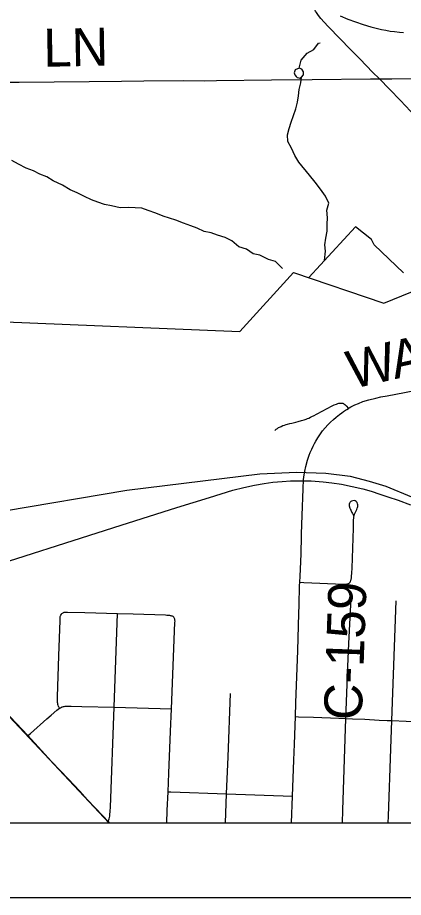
# Model space of a CAD drawing. Extents: x 0 to 34, y 0 to 22.
# Drawn here: x 14.164 to 14.741, y 9.81 to 11.126 of the extents above; entities that cross this region are included whole.
import ezdxf

# ---------------------------------------------------------------- set-up
doc = ezdxf.new("R2010")
doc.units = 0
for name, color, linetype in [('GM_X_Corporation', 7, 'Continuous'), ('GM_X_County_Road', 7, 'Continuous'), ('GM_X_County_Road_Text', 7, 'Continuous'), ('GM_X_Minor_Lake', 7, 'Continuous'), ('GM_X_Minor_River', 7, 'Continuous'), ('GM_X_Rail_Line', 7, 'Continuous'), ('GM_X_State_Route', 7, 'Continuous'), ('GM_X_Township_Road', 7, 'Continuous'), ('SH_Data', 7, 'Continuous')]:
    doc.layers.add(name, color=color, linetype=linetype)

msp = doc.modelspace()

# ---------------------------------------------------------------- linework, layer by layer
at = {"layer": 'GM_X_Corporation'}
msp.add_lwpolyline([(13.1086, 12.6609), (13.111, 11.8906), (13.114, 11.5469), (13.1204, 10.132), (13.1218, 9.9288), (13.1219, 9.9214), (18.7033, 9.9214)], dxfattribs=at)
at = {"layer": 'GM_X_County_Road'}
for p, q in [((14.5737, 9.9214), (14.5753, 9.961)), ((14.2995, 9.9234), (14.3014, 9.9214))]:
    msp.add_line(p, q, dxfattribs=at)
for points in [[(14.7052, 11.0345), (14.6952, 11.0447), (14.6764, 11.0637), (14.6612, 11.0792), (14.647, 11.0939), (14.6283, 11.1131), (14.6179, 11.1246), (14.6157, 11.1272), (14.6131, 11.1305), (14.6111, 11.1335), (14.6097, 11.1358), (14.6085, 11.1378), (14.6075, 11.1401), (14.6067, 11.1424), (14.6062, 11.1445), (14.6059, 11.1466), (14.6056, 11.1505)], [(14.127, 11.0295), (14.1666, 11.0294), (14.2711, 11.0304), (14.3194, 11.031), (14.3528, 11.0315), (14.4117, 11.0318), (14.444, 11.0317), (14.4619, 11.032), (14.5438, 11.0332), (14.6047, 11.0334), (14.692, 11.0344), (14.7052, 11.0345)], [(14.7052, 11.0345), (14.7237, 11.0347), (14.7658, 11.035), (14.8162, 11.0357), (14.8668, 11.0361), (14.9479, 11.0368), (15.0064, 11.0372), (15.0495, 11.0372)], [(14.8686, 10.8663), (14.8564, 10.879), (14.8361, 10.9), (14.8187, 10.9177), (14.8014, 10.9356), (14.7848, 10.9524), (14.7688, 10.9689), (14.7518, 10.9862), (14.7368, 11.0019), (14.7205, 11.019), (14.7052, 11.0345)], [(14.659, 10.5414), (14.66, 10.542), (14.6628, 10.5436), (14.6687, 10.5465), (14.6739, 10.5489), (14.6805, 10.5515), (14.6896, 10.5544), (14.6999, 10.5569), (14.7076, 10.5585), (14.7171, 10.5603), (14.7427, 10.5651), (14.7653, 10.5696), (14.7904, 10.5747), (14.7959, 10.5759), (14.8013, 10.5772), (14.8052, 10.5782), (14.8087, 10.5793), (14.812, 10.5805), (14.8157, 10.5819), (14.8211, 10.5842), (14.8301, 10.5886), (14.8501, 10.6)], [(14.6069, 10.5305), (14.6122, 10.5334), (14.6344, 10.545), (14.6376, 10.5465), (14.6409, 10.5479), (14.6432, 10.5487), (14.6448, 10.5491), (14.6466, 10.5493), (14.6473, 10.5494), (14.6485, 10.5494), (14.6492, 10.5494), (14.6504, 10.5491), (14.6517, 10.5486), (14.6523, 10.5483), (14.6534, 10.5473), (14.6554, 10.5453), (14.659, 10.5414)], [(14.5886, 10.3412), (14.5889, 10.3514), (14.589, 10.3538), (14.5898, 10.3811), (14.5911, 10.4209), (14.592, 10.4351), (14.5928, 10.4419), (14.5937, 10.4477), (14.5951, 10.4546), (14.5977, 10.4641), (14.6002, 10.4712), (14.6019, 10.4755), (14.6041, 10.4806), (14.6061, 10.4847), (14.6084, 10.489), (14.6104, 10.4925), (14.6134, 10.4975), (14.6162, 10.5017), (14.6204, 10.5077), (14.6242, 10.5123), (14.6281, 10.5168), (14.6322, 10.521), (14.6364, 10.5248), (14.6408, 10.5285), (14.6454, 10.5321), (14.649, 10.5348), (14.6517, 10.5367), (14.6547, 10.5387), (14.6566, 10.5399), (14.659, 10.5414)], [(14.5487, 10.5084), (14.551, 10.5101), (14.5529, 10.5115), (14.5546, 10.5126), (14.5559, 10.5133), (14.5573, 10.514), (14.5582, 10.5145), (14.5608, 10.5156), (14.5634, 10.5165), (14.5658, 10.5172), (14.5678, 10.5177), (14.5713, 10.5186), (14.5743, 10.5194), (14.5802, 10.5208), (14.584, 10.5218), (14.5889, 10.5232), (14.5926, 10.5243), (14.5956, 10.5253), (14.5979, 10.5262), (14.5999, 10.527), (14.6022, 10.5281), (14.6051, 10.5296), (14.6069, 10.5305)], [(14.5863, 10.2812), (14.5867, 10.2903), (14.5877, 10.312), (14.5881, 10.3244), (14.5885, 10.3349), (14.5886, 10.3392), (14.5886, 10.3412)], [(14.5796, 10.0803), (14.5803, 10.1011), (14.5834, 10.1794), (14.585, 10.2344), (14.5853, 10.2468), (14.586, 10.276), (14.5863, 10.2812)], [(14.1348, 10.0917), (14.1376, 10.0905), (14.1399, 10.0894), (14.1422, 10.0882), (14.1447, 10.0866), (14.1474, 10.0847), (14.1527, 10.0802), (14.1628, 10.07), (14.1796, 10.0518)], [(14.5753, 9.961), (14.5772, 10.0153), (14.5781, 10.0388), (14.5796, 10.0803)], [(14.1796, 10.0518), (14.1999, 10.0298), (14.2149, 10.0133), (14.2401, 9.9867), (14.2572, 9.9687), (14.269, 9.9559), (14.2915, 9.9319), (14.2995, 9.9234)]]:
    msp.add_lwpolyline(points, dxfattribs=at)
at = {"layer": 'GM_X_Minor_Lake'}
msp.add_line((14.5786, 11.0406), (14.5807, 11.0379), dxfattribs=at)
msp.add_lwpolyline([(14.5807, 11.0379), (14.5822, 11.0365), (14.5849, 11.0358), (14.5864, 11.0354), (14.589, 11.037), (14.5917, 11.0404), (14.5916, 11.045), (14.5893, 11.0491), (14.5851, 11.0506), (14.5791, 11.0479), (14.5776, 11.0433), (14.5786, 11.0406)], dxfattribs=at)
at = {"layer": 'GM_X_Minor_River'}
for p, q in [((14.6695, 10.8131), (14.5997, 10.737)), ((14.6935, 10.7943), (14.6695, 10.8131)), ((14.6977, 10.786), (14.6935, 10.7943)), ((14.7412, 10.7441), (14.6977, 10.786)), ((14.4966, 10.6567), (14.5766, 10.7449)), ((14.5766, 10.7449), (14.7117, 10.6989)), ((14.7117, 10.6989), (14.7655, 10.7206)), ((14.126, 10.6717), (14.4966, 10.6567))]:
    msp.add_line(p, q, dxfattribs=at)
for points in [[(14.5851, 11.0506), (14.5881, 11.0624), (14.5971, 11.0727), (14.6072, 11.0784), (14.6144, 11.088), (14.6166, 11.0884)], [(14.6231, 10.7625), (14.6248, 10.7764), (14.6236, 10.7862), (14.6254, 10.7961), (14.6272, 10.8067), (14.6271, 10.817), (14.6278, 10.8264), (14.6265, 10.8382), (14.6299, 10.8485), (14.6249, 10.8587), (14.6172, 10.8696), (14.6092, 10.8798), (14.6008, 10.8903), (14.5847, 10.9099), (14.5786, 10.9197), (14.5736, 10.9307), (14.5682, 10.9409), (14.5678, 10.9507), (14.5703, 10.9602), (14.5733, 10.9697), (14.577, 10.9796), (14.5803, 10.9895), (14.5829, 10.9998), (14.5843, 11.0093), (14.5854, 11.0187), (14.588, 11.0286), (14.5889, 11.0369)], [(14.5602, 10.7505), (14.5499, 10.761), (14.5393, 10.7643), (14.5264, 10.7707), (14.5165, 10.7725), (14.5063, 10.7796), (14.4953, 10.783), (14.4846, 10.792), (14.4747, 10.7972), (14.4633, 10.8005), (14.4535, 10.8042), (14.4432, 10.8061), (14.433, 10.8109), (14.4231, 10.8146), (14.4121, 10.8183), (14.4011, 10.8228), (14.3912, 10.8258), (14.3817, 10.8291), (14.3711, 10.8336), (14.3597, 10.8373), (14.3499, 10.841), (14.34, 10.8413), (14.3302, 10.842), (14.3177, 10.8415), (14.3048, 10.8444), (14.2942, 10.8463), (14.2843, 10.85), (14.2748, 10.8537), (14.2642, 10.8582), (14.2535, 10.8638), (14.2429, 10.8686), (14.2315, 10.8753), (14.2174, 10.8817), (14.2079, 10.8877), (14.1977, 10.8918), (14.1878, 10.897), (14.1768, 10.9007), (14.1658, 10.9067), (14.1555, 10.9123)]]:
    msp.add_lwpolyline(points, dxfattribs=at)
at = {"layer": 'GM_X_Rail_Line'}
for points in [[(14.1444, 10.3883), (14.3278, 10.419), (14.5263, 10.4433), (14.5815, 10.446), (14.6252, 10.4446), (14.6618, 10.4398), (14.6899, 10.4325), (14.7147, 10.4251), (14.7535, 10.4092), (15.1648, 10.2215), (15.268, 10.1707), (15.3613, 10.1307), (15.4037, 10.1062)], [(14.0907, 10.294), (14.3192, 10.3667), (14.4022, 10.3931), (14.451, 10.4082), (14.4862, 10.419), (14.5025, 10.4232), (14.5187, 10.4264), (14.5331, 10.429), (14.546, 10.4309), (14.56, 10.4322), (14.5724, 10.4328), (14.5852, 10.4332), (14.6034, 10.4328), (14.6211, 10.4316), (14.634, 10.4301), (14.6488, 10.4279), (14.6646, 10.4246), (14.6806, 10.4209), (14.693, 10.4176), (14.706, 10.4132), (14.7178, 10.4093), (14.7332, 10.404), (14.7516, 10.3973)], [(14.3009, 9.9214), (14.1369, 10.0957), (13.4469, 10.121), (13.3674, 10.1227)]]:
    msp.add_lwpolyline(points, dxfattribs=at)
at = {"layer": 'GM_X_State_Route'}
msp.add_lwpolyline([(14.6466, 11.1286), (14.6581, 11.1238), (14.6697, 11.1196), (14.6811, 11.1158), (14.6925, 11.1124), (14.7025, 11.1098), (14.7083, 11.1085), (14.7151, 11.1071), (14.7216, 11.106), (14.7278, 11.1051), (14.7351, 11.1042), (14.7415, 11.1037)], dxfattribs=at)
at = {"layer": 'GM_X_Township_Road'}
for p, q in [((14.7238, 10.0742), (14.7304, 10.2535)), ((14.3084, 10.0943), (14.3135, 10.2347)), ((14.3084, 10.0943), (14.3942, 10.0919)), ((14.4749, 9.9214), (14.4767, 9.9645)), ((14.4767, 9.9645), (14.5753, 9.961))]:
    msp.add_line(p, q, dxfattribs=at)
for points in [[(14.6608, 10.2806), (14.6614, 10.2813), (14.662, 10.2823), (14.6623, 10.2829), (14.6626, 10.2838), (14.6628, 10.2844), (14.663, 10.2853), (14.6632, 10.2862), (14.6634, 10.2875), (14.6635, 10.2885), (14.6636, 10.2901), (14.664, 10.2952), (14.6644, 10.3025), (14.6663, 10.3621), (14.6666, 10.3726), (14.6667, 10.3755), (14.6668, 10.3765), (14.6669, 10.378), (14.667, 10.3787), (14.6671, 10.3797), (14.6673, 10.3806), (14.6676, 10.3816), (14.6682, 10.3833), (14.6689, 10.3851), (14.6695, 10.3863), (14.6715, 10.3901), (14.6722, 10.3919), (14.6726, 10.393), (14.6728, 10.3945), (14.6729, 10.3958), (14.6729, 10.3971), (14.6726, 10.3985), (14.6718, 10.4005), (14.6704, 10.4021), (14.6691, 10.403), (14.6673, 10.4034), (14.6655, 10.4033), (14.6638, 10.4028), (14.6625, 10.4019), (14.6616, 10.401), (14.6611, 10.4003), (14.6607, 10.3994), (14.6603, 10.3983), (14.6602, 10.3976), (14.6602, 10.3962), (14.6603, 10.3952), (14.6604, 10.3944), (14.6607, 10.3935), (14.6611, 10.3923), (14.6615, 10.3914), (14.6626, 10.3891), (14.6643, 10.3857), (14.6652, 10.384), (14.6667, 10.3813)], [(14.5863, 10.2812), (14.5924, 10.2809), (14.6518, 10.2786), (14.6543, 10.2786), (14.6567, 10.2787), (14.6579, 10.279), (14.6591, 10.2794), (14.66, 10.2799), (14.6608, 10.2806)], [(14.6552, 10.0774), (14.656, 10.1022), (14.6583, 10.155), (14.6597, 10.1896), (14.6629, 10.2571)], [(14.2269, 10.0928), (14.2263, 10.094), (14.2259, 10.0948), (14.2255, 10.0955), (14.2247, 10.0973), (14.2245, 10.098), (14.2244, 10.0987), (14.2242, 10.0998), (14.2241, 10.1014), (14.224, 10.105), (14.224, 10.1101), (14.2259, 10.1711), (14.2277, 10.2242), (14.2278, 10.2268), (14.2279, 10.2285), (14.2281, 10.2301), (14.2285, 10.2312), (14.2288, 10.2322), (14.2297, 10.2335), (14.2304, 10.2344), (14.2313, 10.2352)], [(14.2313, 10.2352), (14.2322, 10.2357), (14.233, 10.236), (14.2338, 10.2363), (14.235, 10.2364), (14.2363, 10.2365), (14.2372, 10.2365), (14.2388, 10.2364), (14.2647, 10.2359), (14.3135, 10.2347)], [(14.3135, 10.2347), (14.3372, 10.2341), (14.3853, 10.2323), (14.3875, 10.2321), (14.3892, 10.232), (14.3905, 10.2319), (14.3912, 10.2318), (14.3924, 10.2316), (14.3934, 10.2314), (14.3945, 10.2312), (14.3954, 10.2309), (14.3963, 10.2305), (14.3974, 10.2297), (14.398, 10.2291)], [(14.3942, 10.0919), (14.3996, 10.2213), (14.3997, 10.2229), (14.3996, 10.2239), (14.3996, 10.225), (14.3994, 10.226), (14.3991, 10.2272), (14.3986, 10.2282), (14.398, 10.2291)], [(14.4767, 9.9645), (14.4789, 10.0203), (14.4826, 10.1147)], [(14.1796, 10.0518), (14.1833, 10.055), (14.2079, 10.0767), (14.2143, 10.0824), (14.2228, 10.0897), (14.2247, 10.0912), (14.2269, 10.0928)], [(14.2269, 10.0928), (14.2283, 10.0936), (14.2297, 10.0944), (14.231, 10.0949), (14.2316, 10.0951), (14.2331, 10.0954), (14.2341, 10.0956), (14.2356, 10.0957), (14.2368, 10.0958), (14.2388, 10.0959), (14.2442, 10.0958), (14.2601, 10.0954), (14.3084, 10.0943)], [(14.2995, 9.9234), (14.301, 9.9272), (14.3016, 9.9293), (14.302, 9.9311), (14.3022, 9.9333), (14.3026, 9.939), (14.303, 9.9449), (14.3084, 10.0943)], [(14.3892, 9.9677), (14.3905, 9.9954), (14.3928, 10.0581), (14.3942, 10.0919)], [(14.5796, 10.0803), (14.5841, 10.0801), (14.6068, 10.0792), (14.6447, 10.0778), (14.6552, 10.0774)], [(14.65, 9.9214), (14.6507, 9.9401), (14.6552, 10.0774)], [(14.6552, 10.0774), (14.6651, 10.077), (14.6837, 10.0762), (14.7048, 10.0751), (14.717, 10.0745), (14.7238, 10.0742)], [(14.7183, 9.9214), (14.7187, 9.9311), (14.7222, 10.0323), (14.7238, 10.0742)], [(14.7238, 10.0742), (14.7452, 10.0736), (14.7694, 10.0731), (14.793, 10.0727)], [(14.3872, 9.9214), (14.3878, 9.9396), (14.3892, 9.9677)], [(14.3892, 9.9677), (14.3933, 9.9675), (14.4767, 9.9645)]]:
    msp.add_lwpolyline(points, dxfattribs=at)
at = {"layer": 'SH_Data'}
msp.add_line((12.556, 9.8098), (19.556, 9.8098), dxfattribs=at)

# ---------------------------------------------------------------- texts
at = {"layer": 'GM_X_County_Road_Text'}
for s, height, rotation, p in [('LN', 0.05682, 1.0317, (14.2032, 11.0525)), ('W', 0.0568, 13.0492, (14.6643, 10.5702)), ('A', 0.0568, 12.1037, (14.7282, 10.585)), ('C-159', 0.05682, 87.9948, (14.6788, 10.0741))]:
    msp.add_text(s, height=height, rotation=rotation, dxfattribs=at).set_placement(p)

doc.saveas('drawing.dxf')
